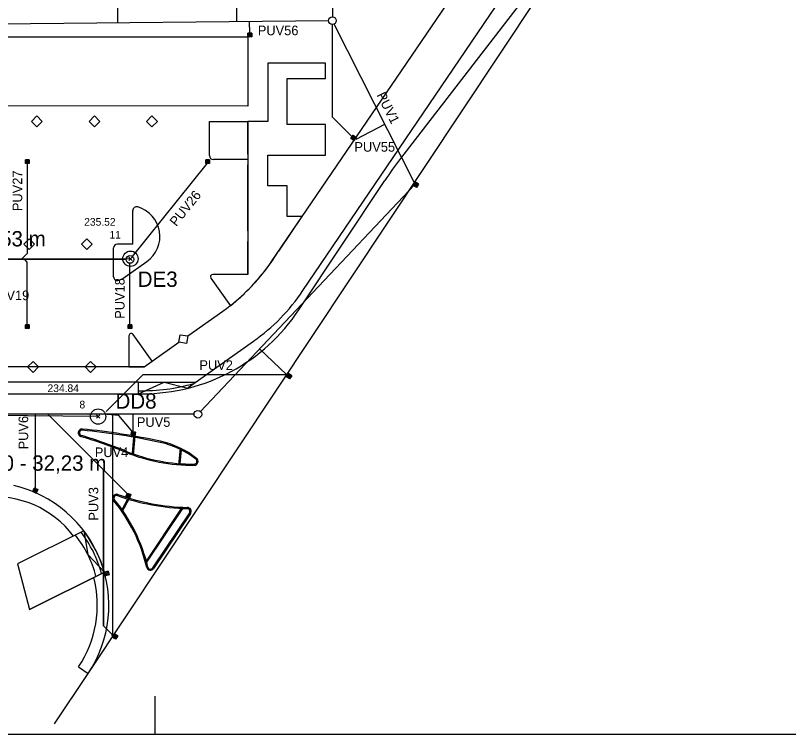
# Model space of a CAD drawing. Extents: x -264234 to -263604, y -1242346 to -1242049.
# Drawn here: x -263832.4 to -263731.6, y -1242345.9 to -1242252.2 of the extents above; entities that cross this region are included whole.
import ezdxf

# ---------------------------------------------------------------- set-up
doc = ezdxf.new("R2010")
doc.units = 0
for name, color, linetype in [('KFA_BODY_CISLO', 7, 'Continuous'), ('KFA_BODY_SYMBOL', 7, 'Continuous'), ('KFA_BODY_VYSKA', 7, 'Continuous'), ('KFA_DAZDOVA_KANALIZACIA_vetva_D', 7, 'Continuous'), ('KFA_DAZDOVA_KANALIZACIA_vetva_D_popis', 7, 'Continuous'), ('KFA_DAZDOVA_KANALIZACIA_vetva_E', 7, 'Continuous'), ('KFA_DAZDOVA_KANALIZACIA_vetva_E_popis', 7, 'Continuous'), ('KFA_JESTV_IS_DSP_-_KANAL_DAZD', 7, 'Continuous'), ('KFA_SITUACIA_DSP', 7, 'Continuous'), ('KFA_SO_40-2-II_DK_PRIPOJKY_UV_PROJEKT', 7, 'Continuous'), ('KFA_SO_40-2-II_DK_PRIPOJKY_UV_PROJEKT_popis', 7, 'Continuous'), ('KFA_SO_40-2-II_DK_UV_PROJEKT', 7, 'Continuous'), ('RAM_NA_TLAC_1-500', 7, 'Continuous')]:
    doc.layers.add(name, color=color, linetype=linetype)

msp = doc.modelspace()

# ---------------------------------------------------------------- linework, layer by layer
at = {"layer": 'KFA_BODY_SYMBOL'}
for p, q in [((-263817.59, -1242284.1), (-263817.15, -1242283.66)), ((-263817.15, -1242284.1), (-263817.59, -1242283.66)), ((-263821.81, -1242304.68), (-263821.37, -1242304.23)), ((-263821.37, -1242304.68), (-263821.81, -1242304.23))]:
    msp.add_line(p, q, dxfattribs=at)
at = {"layer": 'KFA_DAZDOVA_KANALIZACIA_vetva_D'}
msp.add_lwpolyline([(-263821.59, -1242304.45), (-263853.82, -1242304.12), (-263903.79, -1242304.32), (-263951.83, -1242303.9), (-264004.17, -1242304.05), (-264044.82, -1242304.22), (-264095.21, -1242304.15), (-264105.62, -1242304.17)], dxfattribs=at)
msp.add_circle((-263821.59, -1242304.45), 1, dxfattribs=at)
at = {"layer": 'KFA_DAZDOVA_KANALIZACIA_vetva_E'}
msp.add_lwpolyline([(-263817.37, -1242283.88), (-263870.9, -1242283.96), (-263904.01, -1242284.08)], dxfattribs=at)
msp.add_circle((-263817.37, -1242283.88), 1, dxfattribs=at)
at = {"layer": 'KFA_JESTV_IS_DSP_-_KANAL_DAZD'}
for p, q in [((-263790.32, -1242212.53), (-263791.05, -1242252.36)), ((-263791.56, -1242252.87), (-263840.16, -1242253.36))]:
    msp.add_line(p, q, dxfattribs=at)
msp.add_circle((-263791.06, -1242252.86), 0.5, dxfattribs=at)
at = {"layer": 'KFA_SITUACIA_DSP'}
for p, q in [((-263822.88, -1242337.91), (-263735.3, -1242206.15)), ((-263794.9, -1242288.03), (-263742.74, -1242211.14)), ((-263798.9, -1242284.13), (-263751.86, -1242215.08)), ((-263752.52, -1242232.37), (-263782.17, -1242270.82)), ((-263803.56, -1242238.31), (-263803.56, -1242252.99)), ((-263819.07, -1242241.13), (-263819.07, -1242253.15)), ((-263801.82, -1242254.5), (-263801.84, -1242252.97)), ((-263791.06, -1242265.43), (-263791.06, -1242253.36)), ((-263802.07, -1242254.7), (-263801.57, -1242254.7)), ((-263802.07, -1242254.99), (-263802.07, -1242254.7)), ((-263802.07, -1242254.7), (-263801.57, -1242254.99)), ((-263802.07, -1242254.7), (-263801.57, -1242254.99)), ((-263801.57, -1242254.7), (-263802.07, -1242254.7)), ((-263801.57, -1242254.99), (-263802.07, -1242254.99)), ((-263801.57, -1242254.7), (-263801.57, -1242254.99)), ((-263801.57, -1242254.99), (-263801.57, -1242254.7)), ((-263807.07, -1242270.45), (-263807.07, -1242265.99)), ((-263807.07, -1242265.99), (-263802.07, -1242265.99)), ((-263802.07, -1242270.24), (-263802.07, -1242265.99)), ((-263788.5, -1242267.99), (-263791.06, -1242265.43)), ((-263788.49, -1242268.32), (-263788.21, -1242267.91)), ((-263788.21, -1242267.91), (-263788.49, -1242268.32)), ((-263788.49, -1242268.32), (-263787.97, -1242268.07)), ((-263788.49, -1242268.32), (-263787.97, -1242268.07)), ((-263787.97, -1242268.07), (-263788.25, -1242268.49)), ((-263788.21, -1242267.91), (-263787.97, -1242268.07)), ((-263787.97, -1242268.07), (-263788.21, -1242267.91)), ((-263788.25, -1242268.49), (-263788.49, -1242268.32)), ((-263831.07, -1242270.98), (-263830.57, -1242270.98)), ((-263831.07, -1242271.27), (-263831.07, -1242270.98)), ((-263831.07, -1242270.98), (-263830.57, -1242271.27)), ((-263831.07, -1242270.98), (-263830.57, -1242271.27)), ((-263830.57, -1242270.98), (-263831.07, -1242270.98)), ((-263830.57, -1242271.27), (-263831.07, -1242271.27)), ((-263830.57, -1242270.98), (-263830.57, -1242271.27)), ((-263830.57, -1242271.27), (-263830.57, -1242270.98)), ((-263807.57, -1242270.98), (-263807.07, -1242270.98)), ((-263807.57, -1242271.27), (-263807.57, -1242270.98)), ((-263807.57, -1242270.98), (-263807.07, -1242271.27)), ((-263807.57, -1242270.98), (-263807.07, -1242271.27)), ((-263807.07, -1242270.98), (-263807.57, -1242270.98)), ((-263807.07, -1242271.27), (-263807.57, -1242271.27)), ((-263807.07, -1242270.98), (-263807.07, -1242271.27)), ((-263807.07, -1242271.27), (-263807.07, -1242270.98)), ((-263802.07, -1242270.95), (-263806.57, -1242270.95)), ((-263830.82, -1242271.47), (-263830.82, -1242283.19)), ((-263807.38, -1242271.45), (-263817.13, -1242283.59)), ((-263802.07, -1242280.24), (-263802.07, -1242271.65)), ((-263780.35, -1242274.24), (-263808.25, -1242303.78)), ((-263795.42, -1242290.54), (-263784.21, -1242273.68)), ((-263780.34, -1242274.43), (-263780.06, -1242274.01)), ((-263780.06, -1242274.01), (-263780.34, -1242274.43)), ((-263780.34, -1242274.43), (-263779.82, -1242274.17)), ((-263780.34, -1242274.43), (-263779.82, -1242274.17)), ((-263779.82, -1242274.17), (-263780.1, -1242274.59)), ((-263780.06, -1242274.01), (-263779.82, -1242274.17)), ((-263779.82, -1242274.17), (-263780.06, -1242274.01)), ((-263780.1, -1242274.59), (-263780.34, -1242274.43)), ((-263817.07, -1242281.98), (-263817.07, -1242277.62)), ((-263817.07, -1242281.98), (-263819.07, -1242281.98)), ((-263802.07, -1242285.95), (-263802.07, -1242281.65)), ((-263830.82, -1242283.19), (-263831.62, -1242283.98)), ((-263819.57, -1242286.23), (-263819.57, -1242282.48)), ((-263817.94, -1242283.98), (-263870.32, -1242283.98)), ((-263817.94, -1242283.98), (-263870.32, -1242283.98)), ((-263830.82, -1242284.34), (-263831.15, -1242283.98)), ((-263830.82, -1242292.49), (-263830.82, -1242284.34)), ((-263818.06, -1242286.25), (-263815.23, -1242284.25)), ((-263817.44, -1242292.49), (-263817.44, -1242284.48)), ((-263809.9, -1242293.95), (-263805.34, -1242290.73)), ((-263831.07, -1242292.69), (-263830.57, -1242292.69)), ((-263831.07, -1242292.98), (-263831.07, -1242292.69)), ((-263831.07, -1242292.69), (-263830.57, -1242292.98)), ((-263831.07, -1242292.69), (-263830.57, -1242292.98)), ((-263830.57, -1242292.69), (-263831.07, -1242292.69)), ((-263830.57, -1242292.98), (-263831.07, -1242292.98)), ((-263830.82, -1242292.69), (-263830.82, -1242292.69)), ((-263830.57, -1242292.69), (-263830.57, -1242292.98)), ((-263830.57, -1242292.98), (-263830.57, -1242292.69)), ((-263817.69, -1242292.69), (-263817.19, -1242292.69)), ((-263817.69, -1242292.98), (-263817.69, -1242292.69)), ((-263817.69, -1242292.69), (-263817.19, -1242292.98)), ((-263817.69, -1242292.69), (-263817.19, -1242292.98)), ((-263817.19, -1242292.69), (-263817.69, -1242292.69)), ((-263817.19, -1242292.98), (-263817.69, -1242292.98)), ((-263817.19, -1242292.69), (-263817.19, -1242292.98)), ((-263817.19, -1242292.98), (-263817.19, -1242292.69)), ((-263814.55, -1242297.24), (-263811.05, -1242294.76)), ((-263809.87, -1242300.67), (-263801.34, -1242294.63)), ((-263797.05, -1242298.95), (-263800.56, -1242295.64)), ((-263815.6, -1242297.98), (-263917.08, -1242297.98)), ((-263797.03, -1242299.29), (-263796.75, -1242298.87)), ((-263796.75, -1242298.87), (-263797.03, -1242299.29)), ((-263797.03, -1242299.29), (-263796.51, -1242299.03)), ((-263797.03, -1242299.29), (-263796.51, -1242299.03)), ((-263796.79, -1242299.45), (-263797.03, -1242299.29)), ((-263796.51, -1242299.03), (-263796.79, -1242299.45)), ((-263796.75, -1242298.87), (-263796.51, -1242299.03)), ((-263796.51, -1242299.03), (-263796.75, -1242298.87)), ((-263816.31, -1242299.98), (-263918.05, -1242299.98)), ((-263816.31, -1242301.48), (-263816.31, -1242299.98)), ((-263816.31, -1242299.98), (-263808.9, -1242299.98)), ((-263914.08, -1242301.48), (-263815.82, -1242301.48)), ((-263809.91, -1242300.76), (-263809.87, -1242300.67)), ((-263809.09, -1242304.15), (-263853.41, -1242304.15)), ((-263829.75, -1242313.86), (-263829.75, -1242304.15)), ((-263819.67, -1242332.82), (-263819.67, -1242304.15)), ((-263817, -1242306.47), (-263817, -1242304.15)), ((-263817.3, -1242306.91), (-263817.25, -1242306.63)), ((-263817.25, -1242306.63), (-263817.3, -1242306.91)), ((-263816.8, -1242306.99), (-263817.3, -1242306.91)), ((-263817.3, -1242306.91), (-263816.8, -1242306.99)), ((-263817.25, -1242306.63), (-263816.76, -1242306.7)), ((-263816.8, -1242306.99), (-263817.25, -1242306.63)), ((-263816.8, -1242306.99), (-263817.25, -1242306.63)), ((-263816.96, -1242307.13), (-263817.15, -1242309.26)), ((-263816.8, -1242307.01), (-263817.01, -1242309.47)), ((-263816.76, -1242306.7), (-263816.8, -1242306.99)), ((-263810.91, -1242308.55), (-263811.1, -1242310.72)), ((-263810.78, -1242308.78), (-263810.93, -1242310.58)), ((-263817.71, -1242314.57), (-263819.67, -1242312.62)), ((-263830.1, -1242314.22), (-263829.98, -1242313.95)), ((-263829.98, -1242313.95), (-263830.1, -1242314.22)), ((-263829.64, -1242314.42), (-263830.1, -1242314.22)), ((-263830.1, -1242314.22), (-263829.64, -1242314.42)), ((-263829.98, -1242313.95), (-263829.53, -1242314.16)), ((-263829.64, -1242314.42), (-263829.98, -1242313.95)), ((-263829.64, -1242314.42), (-263829.98, -1242313.95)), ((-263829.53, -1242314.16), (-263829.64, -1242314.42)), ((-263818.47, -1242316.58), (-263817.71, -1242315.18)), ((-263818.45, -1242316.87), (-263817.49, -1242315.09)), ((-263817.97, -1242314.94), (-263817.87, -1242314.67)), ((-263817.87, -1242314.67), (-263817.97, -1242314.94)), ((-263817.49, -1242315.1), (-263817.97, -1242314.94)), ((-263817.97, -1242314.94), (-263817.49, -1242315.1)), ((-263817.87, -1242314.67), (-263817.4, -1242314.82)), ((-263817.49, -1242315.1), (-263817.87, -1242314.67)), ((-263817.49, -1242315.1), (-263817.87, -1242314.67)), ((-263817.4, -1242314.82), (-263817.49, -1242315.1)), ((-263810.75, -1242316.41), (-263815.43, -1242323.41)), ((-263810.58, -1242316.41), (-263815.27, -1242323.44)), ((-263809.68, -1242316.98), (-263814.48, -1242324.17)), ((-263809.55, -1242317.06), (-263814.36, -1242324.25)), ((-263823.44, -1242319.35), (-263832.11, -1242323.65)), ((-263813.54, -1242320.69), (-263813.54, -1242320.69)), ((-263813.54, -1242320.69), (-263813.54, -1242320.69)), ((-263832.11, -1242323.65), (-263830.54, -1242329.57)), ((-263820.77, -1242324.72), (-263830.54, -1242329.57)), ((-263819.72, -1242333.19), (-263819.44, -1242332.77)), ((-263819.72, -1242333.19), (-263819.2, -1242332.93)), ((-263819.48, -1242333.35), (-263819.72, -1242333.19)), ((-263819.2, -1242332.93), (-263819.48, -1242333.35)), ((-263819.44, -1242332.77), (-263819.2, -1242332.93)), ((-263824.13, -1242337.08), (-263822.88, -1242337.91)), ((-263827.28, -1242344.5), (-263822.88, -1242337.91))]:
    msp.add_line(p, q, dxfattribs=at)
for points in [[(-263802.07, -1242263.99), (-263834.26, -1242263.98), (-263849.47, -1242254.98), (-263802.07, -1242254.99)], [(-263829.57, -1242265.28), (-263828.86, -1242265.99), (-263829.57, -1242266.69), (-263830.27, -1242265.99)], [(-263822.07, -1242265.28), (-263821.36, -1242265.99), (-263822.07, -1242266.69), (-263822.77, -1242265.99)], [(-263814.57, -1242265.28), (-263813.86, -1242265.99), (-263814.57, -1242266.69), (-263815.27, -1242265.99)], [(-263830.57, -1242281.28), (-263829.86, -1242281.98), (-263830.57, -1242282.69), (-263831.27, -1242281.98)], [(-263823.07, -1242281.28), (-263822.36, -1242281.98), (-263823.07, -1242282.69), (-263823.77, -1242281.98)], [(-263810.88, -1242293.78), (-263809.9, -1242293.95), (-263810.06, -1242294.93), (-263811.05, -1242294.76)], [(-263830.07, -1242297.28), (-263829.36, -1242297.98), (-263830.07, -1242298.69), (-263830.77, -1242297.98)], [(-263822.57, -1242297.28), (-263821.86, -1242297.98), (-263822.57, -1242298.69), (-263823.27, -1242297.98)], [(-263819.72, -1242333.19), (-263819.2, -1242332.93), (-263819.44, -1242332.77)]]:
    msp.add_lwpolyline(points, close=True, dxfattribs=at)
for points in [[(-263798.06, -1242282.88), (-263794.99, -1242278.38), (-263796.97, -1242278.38), (-263796.97, -1242274.38), (-263799.47, -1242274.38), (-263799.47, -1242270.38), (-263791.97, -1242270.38), (-263791.97, -1242266.38), (-263796.97, -1242266.38), (-263796.97, -1242260.38), (-263791.97, -1242260.38), (-263791.97, -1242258.38), (-263799.47, -1242258.38), (-263799.47, -1242265.99), (-263802.07, -1242265.99)], [(-263802.07, -1242265.99), (-263802.07, -1242270.24), (-263802.07, -1242270.95), (-263802.07, -1242271.65), (-263802.07, -1242273.45), (-263802.07, -1242275.95), (-263802.07, -1242278.45), (-263802.07, -1242280.24), (-263802.07, -1242280.24), (-263802.07, -1242281.65), (-263802.07, -1242283.45), (-263802.07, -1242285.95), (-263806.66, -1242285.94)], [(-263806.9, -1242286.42), (-263804.35, -1242290.02), (-263802.55, -1242288.44)], [(-263817.57, -1242293.93), (-263817.57, -1242297.98), (-263815.6, -1242297.98), (-263814.55, -1242297.24), (-263817.02, -1242293.75)], [(-263816.33, -1242301.51), (-263813, -1242299.98), (-263809.91, -1242300.76)], [(-263832.11, -1242323.65), (-263830.54, -1242329.57), (-263820.77, -1242324.72), (-263821.24, -1242323.31), (-263821.84, -1242321.94), (-263822.87, -1242320.15), (-263823.44, -1242319.35), (-263832.11, -1242323.65)], [(-263823.44, -1242319.35), (-263822.93, -1242322.44), (-263820.77, -1242324.72)]]:
    msp.add_lwpolyline(points, dxfattribs=at)
for centre, radius in [((-263801.82, -1242254.6), 0.1), ((-263788.43, -1242268.06), 0.1), ((-263830.82, -1242271.37), 0.1), ((-263807.32, -1242271.37), 0.1), ((-263780.28, -1242274.16), 0.1), ((-263817.44, -1242283.98), 0.5), ((-263830.82, -1242292.59), 0.1), ((-263817.44, -1242292.59), 0.1), ((-263796.98, -1242299.02), 0.1), ((-263808.59, -1242304.15), 0.5), ((-263817, -1242306.57), 0.1), ((-263829.75, -1242313.96), 0.1), ((-263817.64, -1242314.64), 0.1), ((-263819.67, -1242332.92), 0.1)]:
    msp.add_circle(centre, radius, dxfattribs=at)
for centre, radius, start, end in [((-263806.57, -1242270.45), 0.5, 180, 270), ((-263742.57, -1242301.35), 50, 142.3688, 146.3992), ((-263816.57, -1242277.62), 0.5, 73.8446, 180), ((-263817.54, -1242280.98), 4, 305.2702, 73.8446), ((-263819.07, -1242282.48), 0.5, 90, 180), ((-263821.81, -1242268.3), 27.86, 313.7192, 328.4502), ((-263820.07, -1242269.91), 25.5, 305.2702, 326.1165), ((-263819.07, -1242286.23), 0.5, 180, 291.8332), ((-263820.37, -1242282.98), 4, 291.8332, 305.2702), ((-263806.66, -1242286.24), 0.3, 89.9436, 215.2702), ((-263816.07, -1242273.82), 25.5, 305.2702, 326.1165), ((-263815.82, -1242276.98), 24.5, 270, 326.3992), ((-263817.27, -1242293.93), 0.3, 35.2702, 180), ((-263815.84, -1242276.97), 24.12, 268.8787, 286.1798), ((-263823.69, -1242306.57), 0.5, 84.5031, 253.3726), ((-263823.69, -1242306.57), 0.35, 84.5031, 253.3726), ((-263832, -1242392.97), 87.14, 77.7452, 84.5031), ((-263832, -1242392.97), 87.29, 77.7452, 84.5031), ((-263842.68, -1242370.17), 65.87, 68.0197, 73.3726), ((-263842.68, -1242370.17), 66.02, 68.0197, 73.3726), ((-263815.91, -1242318.9), 11.35, 51.4912, 77.7452), ((-263815.91, -1242318.9), 11.5, 51.4912, 77.7452), ((-263809.23, -1242287.3), 23.5, 248.0197, 270.4085), ((-263809.23, -1242287.3), 23.35, 248.0197, 270.4085), ((-263809.06, -1242310.29), 0.5, 270.4085, 51.4912), ((-263809.06, -1242310.29), 0.35, 270.4085, 51.4912), ((-263836.18, -1242329.03), 16, 326.2529, 76.9695), ((-263819.18, -1242315.07), 0.5, 70.2828, 219.3857), ((-263809.23, -1242287.3), 29, 250.2828, 268.5641), ((-263835.04, -1242327.71), 12.8, 36.9205, 96.0874), ((-263836.18, -1242329.03), 21.5, 13.267, 39.3857), ((-263819.18, -1242315.07), 0.35, 70.2828, 219.3857), ((-263836.18, -1242329.03), 21.65, 13.267, 39.3857), ((-263809.23, -1242287.3), 29.15, 250.2828, 268.5641), ((-263809.97, -1242316.79), 0.35, 326.2529, 88.5641), ((-263809.97, -1242316.79), 0.5, 326.2529, 88.5641), ((-263836.18, -1242329.03), 15.6, 15.3332, 37.5082), ((-263836.18, -1242329.03), 14.8, 14.7256, 38.1157), ((-263836.18, -1242329.03), 21.65, 13.267, 14.9596), ((-263814.77, -1242323.98), 0.5, 193.267, 326.2529), ((-263814.77, -1242323.98), 0.35, 193.267, 326.2529), ((-263836.23, -1242329.02), 14.54, 326.3344, 14.4166)]:
    msp.add_arc(centre, radius, start, end, dxfattribs=at)
at = {"layer": 'KFA_SO_40-2-II_DK_PRIPOJKY_UV_PROJEKT'}
for p, q in [((-263828.13, -1242304.15), (-263820.88, -1242311.4)), ((-263820.89, -1242311.39), (-263820.89, -1242331.7)), ((-263820.88, -1242311.4), (-263817.71, -1242314.57)), ((-263820.89, -1242331.7), (-263819.74, -1242332.85))]:
    msp.add_line(p, q, dxfattribs=at)
for points in [[(-263801.82, -1242254.5), (-263801.84, -1242252.97)], [(-263780.33, -1242274.07), (-263790.84, -1242253.31)], [(-263787.94, -1242268.29), (-263784.23, -1242266.36)], [(-263830.82, -1242271.47), (-263830.82, -1242283.19), (-263831.62, -1242283.98)], [(-263807.38, -1242271.45), (-263817.13, -1242283.59)], [(-263830.82, -1242292.49), (-263830.82, -1242284.34), (-263831.15, -1242283.98)], [(-263817.44, -1242292.49), (-263817.44, -1242284.48)], [(-263797.08, -1242299.02), (-263815.76, -1242299.02), (-263820.54, -1242303.79)], [(-263829.75, -1242313.86), (-263829.75, -1242304.15)], [(-263828.13, -1242304.15), (-263820.88, -1242311.4), (-263817.71, -1242314.57)], [(-263817.06, -1242306.48), (-263818.89, -1242304.32), (-263820.39, -1242304.19)], [(-263819.74, -1242332.85), (-263820.89, -1242331.7), (-263820.89, -1242311.39)]]:
    msp.add_lwpolyline(points, dxfattribs=at)
at = {"layer": 'KFA_SO_40-2-II_DK_UV_PROJEKT'}
for points in [[(-263802.07, -1242254.99), (-263802.07, -1242254.49), (-263801.57, -1242254.49), (-263801.57, -1242254.99), (-263802.07, -1242254.99), (-263801.57, -1242254.49), (-263802.07, -1242254.49), (-263801.57, -1242254.99)], [(-263788.25, -1242268.49), (-263788.66, -1242268.2), (-263788.37, -1242267.79), (-263787.96, -1242268.08), (-263788.25, -1242268.49), (-263788.37, -1242267.79), (-263788.66, -1242268.2), (-263787.96, -1242268.08)], [(-263831.07, -1242271.48), (-263831.07, -1242270.98), (-263830.57, -1242270.98), (-263830.57, -1242271.48), (-263831.07, -1242271.48), (-263830.57, -1242270.98), (-263831.07, -1242270.98), (-263830.57, -1242271.48)], [(-263807.57, -1242271.48), (-263807.57, -1242270.98), (-263807.07, -1242270.98), (-263807.07, -1242271.48), (-263807.57, -1242271.48), (-263807.07, -1242270.98), (-263807.57, -1242270.98), (-263807.07, -1242271.48)], [(-263780.55, -1242274.29), (-263780.27, -1242273.87), (-263779.85, -1242274.15), (-263780.13, -1242274.57), (-263780.55, -1242274.29), (-263779.85, -1242274.15), (-263780.27, -1242273.87), (-263780.13, -1242274.57)], [(-263831.07, -1242292.98), (-263831.07, -1242292.48), (-263830.57, -1242292.48), (-263830.57, -1242292.98), (-263831.07, -1242292.98), (-263830.57, -1242292.48), (-263831.07, -1242292.48), (-263830.57, -1242292.98)], [(-263817.69, -1242292.98), (-263817.69, -1242292.48), (-263817.19, -1242292.48), (-263817.19, -1242292.98), (-263817.69, -1242292.98), (-263817.19, -1242292.48), (-263817.69, -1242292.48), (-263817.19, -1242292.98)], [(-263797.05, -1242299.27), (-263796.77, -1242298.86), (-263796.35, -1242299.13), (-263796.63, -1242299.55), (-263797.05, -1242299.27), (-263796.35, -1242299.13), (-263796.77, -1242298.86), (-263796.63, -1242299.55)], [(-263817.3, -1242306.91), (-263817.22, -1242306.42), (-263816.73, -1242306.5), (-263816.8, -1242306.99), (-263817.3, -1242306.91), (-263816.73, -1242306.5), (-263817.22, -1242306.42), (-263816.8, -1242306.99)], [(-263830.1, -1242314.22), (-263829.9, -1242313.76), (-263829.44, -1242313.97), (-263829.64, -1242314.42), (-263830.1, -1242314.22), (-263829.44, -1242313.97), (-263829.9, -1242313.76), (-263829.64, -1242314.42)], [(-263817.97, -1242314.94), (-263817.81, -1242314.47), (-263817.33, -1242314.62), (-263817.49, -1242315.1), (-263817.97, -1242314.94), (-263817.33, -1242314.62), (-263817.81, -1242314.47), (-263817.49, -1242315.1)], [(-263820.64, -1242325.2), (-263820.77, -1242324.72), (-263820.29, -1242324.59), (-263820.16, -1242325.07), (-263820.64, -1242325.2), (-263820.29, -1242324.59), (-263820.77, -1242324.72), (-263820.16, -1242325.07)], [(-263819.72, -1242333.19), (-263819.44, -1242332.77), (-263819.03, -1242333.05), (-263819.31, -1242333.47), (-263819.72, -1242333.19), (-263819.03, -1242333.05), (-263819.44, -1242332.77), (-263819.31, -1242333.47)]]:
    msp.add_lwpolyline(points, dxfattribs=at)
at = {"layer": 'RAM_NA_TLAC_1-500'}
msp.add_line((-263814.18, -1242340.88), (-263814.18, -1242345.88), dxfattribs=at)
msp.add_lwpolyline([(-264234.18, -1242048.88), (-263604.18, -1242048.88), (-263604.18, -1242345.88), (-264234.18, -1242345.88)], close=True, dxfattribs=at)

# ---------------------------------------------------------------- texts
at = {"layer": 'KFA_BODY_CISLO'}
for s, p in [('11', (-263820.1, -1242281.26)), ('8', (-263824.02, -1242303.39))]:
    msp.add_text(s, height=1, dxfattribs=at).set_placement(p)
at = {"layer": 'KFA_BODY_VYSKA'}
for s, p in [('235.52', (-263823.4, -1242279.58)), ('234.84', (-263828.18, -1242301.26))]:
    msp.add_text(s, height=1, dxfattribs=at).set_placement(p)
at = {"layer": 'KFA_DAZDOVA_KANALIZACIA_vetva_D_popis'}
for s, p in [('DD8', (-263819.32, -1242303.42)), ('D, PVC DN300 - 32,23 m', (-263850.54, -1242311.51))]:
    msp.add_text(s, height=2, dxfattribs=at).set_placement(p)
at = {"layer": 'KFA_DAZDOVA_KANALIZACIA_vetva_E_popis'}
for s, p in [('E, PVC DN300 - 53,53 m', (-263858.29, -1242282.28)), ('DE3', (-263816.43, -1242287.55))]:
    msp.add_text(s, height=2, dxfattribs=at).set_placement(p)
at = {"layer": 'KFA_SO_40-2-II_DK_PRIPOJKY_UV_PROJEKT_popis'}
for s, p in [('PUV56', (-263800.78, -1242254.76)), ('PUV55', (-263788.19, -1242269.94)), ('PUV19', (-263835.86, -1242289.28)), ('PUV2', (-263808.39, -1242298.37)), ('PUV5', (-263816.54, -1242305.79)), ('PUV4', (-263822.02, -1242309.73))]:
    msp.add_text(s, height=1.25, dxfattribs=at).set_placement(p)
for s, rotation, p in [('PUV1', 296.8422, (-263785.34, -1242262.55)), ('PUV27', 90, (-263831.48, -1242277.68)), ('PUV26', 51.2443, (-263811.4, -1242279.76)), ('PUV18', 90, (-263818.14, -1242291.71)), ('PUV6', 90, (-263830.7, -1242308.73)), ('PUV3', 90, (-263821.56, -1242318.01))]:
    msp.add_text(s, height=1.25, rotation=rotation, dxfattribs=at).set_placement(p)

doc.saveas('drawing.dxf')
